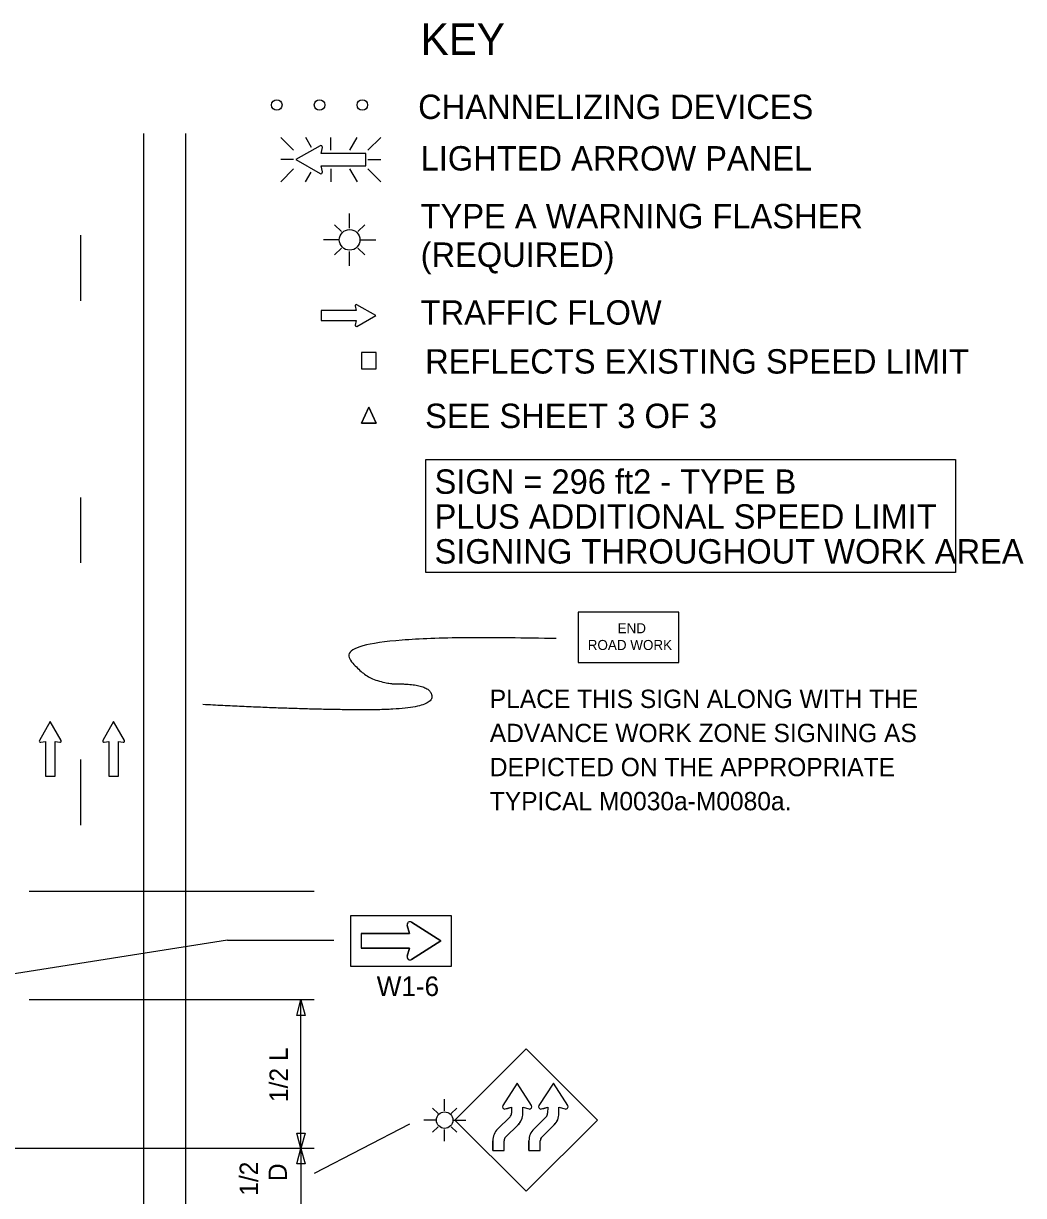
# Model space of a CAD drawing. Extents: x 16544 to 19504, y 5662 to 6922.
# Drawn here: x 17061.7 to 17442.9, y 6474.9 to 6922 of the extents above; entities that cross this region are included whole.
import ezdxf

# ---------------------------------------------------------------- set-up
doc = ezdxf.new("R2010")
doc.units = 0
for name, color, linetype in [('ALI_LEGAL_EX', 7, 'Continuous'), ('MT_SCRATCH_LEVEL_E', 7, 'Continuous'), ('PAVT_EDGE_EX', 7, 'Continuous'), ('TRAFFIC_SIGNS_PR', 7, 'Continuous'), ('TYPICAL_TEXT_DIMEN_EX', 7, 'Continuous'), ('TYPICAL_TEXT_DIMEN_PR', 7, 'Continuous')]:
    doc.layers.add(name, color=color, linetype=linetype)

msp = doc.modelspace()

# ---------------------------------------------------------------- linework, layer by layer
at = {"layer": 'ALI_LEGAL_EX'}
for points in [[(17083.46, 6841.23), (17083.46, 6816.23)], [(17083.46, 6741.23), (17083.46, 6716.23)], [(17083.46, 6641.23), (17083.46, 6616.23)]]:
    msp.add_lwpolyline(points, dxfattribs=at)
at = {"layer": 'MT_SCRATCH_LEVEL_E'}
for p, q in [((17188.13, 6814.25), (17188.44, 6812.47)), ((17188.13, 6814.25), (17188.44, 6812.47)), ((17196.05, 6810.62), (17188.81, 6814.73)), ((17196.05, 6810.62), (17188.81, 6814.73)), ((17188.44, 6812.47), (17175.19, 6812.47)), ((17175.19, 6812.47), (17175.19, 6808.73)), ((17188.44, 6812.47), (17175.19, 6812.47)), ((17175.19, 6812.47), (17175.19, 6808.73)), ((17188.81, 6806.47), (17196.05, 6810.62)), ((17188.81, 6806.47), (17196.05, 6810.62)), ((17175.19, 6808.73), (17188.44, 6808.73)), ((17175.19, 6808.73), (17188.44, 6808.73)), ((17188.44, 6808.73), (17188.13, 6806.95)), ((17188.44, 6808.73), (17188.13, 6806.95)), ((17071.87, 6655.73), (17067.76, 6648.49)), ((17071.87, 6655.73), (17067.76, 6648.49)), ((17076.02, 6648.49), (17071.87, 6655.73)), ((17076.02, 6648.49), (17071.87, 6655.73)), ((17096.04, 6655.73), (17091.93, 6648.49)), ((17096.04, 6655.73), (17091.93, 6648.49)), ((17100.19, 6648.49), (17096.04, 6655.73)), ((17100.19, 6648.49), (17096.04, 6655.73)), ((17068.24, 6647.81), (17070.02, 6648.12)), ((17068.24, 6647.81), (17070.02, 6648.12)), ((17070.02, 6648.12), (17070.02, 6634.86)), ((17070.02, 6648.12), (17070.02, 6634.86)), ((17073.76, 6634.86), (17073.76, 6648.12)), ((17073.76, 6648.12), (17075.54, 6647.81)), ((17073.76, 6634.86), (17073.76, 6648.12)), ((17073.76, 6648.12), (17075.54, 6647.81)), ((17092.41, 6647.81), (17094.19, 6648.12)), ((17092.41, 6647.81), (17094.19, 6648.12)), ((17094.19, 6648.12), (17094.19, 6634.86)), ((17094.19, 6648.12), (17094.19, 6634.86)), ((17097.93, 6634.86), (17097.93, 6648.12)), ((17097.93, 6648.12), (17099.71, 6647.81)), ((17097.93, 6634.86), (17097.93, 6648.12)), ((17097.93, 6648.12), (17099.71, 6647.81)), ((17070.02, 6634.86), (17073.76, 6634.86)), ((17070.02, 6634.86), (17073.76, 6634.86)), ((17094.19, 6634.86), (17097.93, 6634.86)), ((17094.19, 6634.86), (17097.93, 6634.86))]:
    msp.add_line(p, q, dxfattribs=at)
for centre, start, end in [((17188.59, 6814.32), 60.4248, 189.9638), ((17188.59, 6814.32), 60.4248, 189.9638), ((17188.59, 6806.88), 170.0362, 299.7731), ((17188.59, 6806.88), 170.0362, 299.7731), ((17075.61, 6648.27), 260.0362, 29.7731), ((17075.61, 6648.27), 260.0362, 29.7731), ((17099.78, 6648.27), 260.0362, 29.7731), ((17099.78, 6648.27), 260.0362, 29.7731), ((17068.17, 6648.26), 150.4248, 279.9638), ((17068.17, 6648.26), 150.4248, 279.9638), ((17092.34, 6648.26), 150.4248, 279.9638), ((17092.34, 6648.26), 150.4248, 279.9638)]:
    msp.add_arc(centre, 0.463, start, end, dxfattribs=at)
at = {"layer": 'PAVT_EDGE_EX'}
for p, q in [((17107.46, 6880.02), (17107.46, 6074.05)), ((17123.46, 6880.02), (17123.46, 6074.05))]:
    msp.add_line(p, q, dxfattribs=at)
at = {"layer": 'TRAFFIC_SIGNS_PR'}
for p, q in [((17159.73, 6878.55), (17164.67, 6873.62)), ((17171.5, 6874.73), (17169.29, 6878.56)), ((17178.82, 6873.62), (17178.82, 6878.56)), ((17186.05, 6873.62), (17188.9, 6878.56)), ((17192.97, 6873.62), (17197.9, 6878.56)), ((17164.67, 6870.07), (17159.73, 6870.07)), ((17192.97, 6870.07), (17197.9, 6870.07)), ((17159.73, 6861.58), (17164.67, 6866.51)), ((17169.25, 6861.57), (17171.36, 6865.24)), ((17178.82, 6866.51), (17178.82, 6861.57)), ((17188.95, 6861.57), (17186.1, 6866.51)), ((17192.97, 6866.51), (17197.9, 6861.57)), ((17182.88, 6842.6), (17180.25, 6845.23)), ((17182.88, 6842.6), (17180.25, 6845.23)), ((17186.02, 6843.9), (17186.02, 6849.52)), ((17186.02, 6843.9), (17186.02, 6849.52)), ((17189.16, 6842.6), (17191.79, 6845.23)), ((17189.16, 6842.6), (17191.79, 6845.23)), ((17182.08, 6839.46), (17176.04, 6839.46)), ((17182.08, 6839.46), (17176.04, 6839.46)), ((17182.88, 6836.33), (17180.25, 6833.7)), ((17182.88, 6836.33), (17180.25, 6833.7)), ((17189.16, 6836.33), (17191.79, 6833.7)), ((17189.16, 6836.33), (17191.79, 6833.7)), ((17189.96, 6839.46), (17196.05, 6839.46)), ((17189.96, 6839.46), (17196.05, 6839.46)), ((17186.02, 6829.52), (17186.02, 6835.03)), ((17186.02, 6829.52), (17186.02, 6835.03)), ((17208.8, 6574.87), (17207.96, 6577.93)), ((17209.64, 6579.18), (17220.8, 6572.07)), ((17190.4, 6574.87), (17208.8, 6574.87)), ((17190.4, 6574.87), (17190.4, 6569.27)), ((17208.8, 6569.27), (17190.4, 6569.27)), ((17207.96, 6566.21), (17208.8, 6569.27)), ((17220.8, 6572.07), (17209.64, 6564.97)), ((17253.3, 6530.86), (17226.15, 6503.71)), ((17280.45, 6503.71), (17253.3, 6530.86)), ((17222.23, 6507.23), (17222.23, 6511.73)), ((17219.72, 6506.19), (17217.61, 6508.29)), ((17224.74, 6506.19), (17226.85, 6508.29)), ((17219.07, 6503.67), (17214.24, 6503.67)), ((17219.71, 6501.16), (17217.61, 6499.05)), ((17224.74, 6501.16), (17226.85, 6499.05)), ((17225.38, 6503.67), (17230.26, 6503.67)), ((17226.15, 6503.71), (17253.3, 6476.56)), ((17242.43, 6500.24), (17247.15, 6504.96)), ((17247.15, 6504.96), (17242.43, 6500.24)), ((17245.48, 6497.19), (17250.2, 6501.91)), ((17245.49, 6497.19), (17250.2, 6501.91)), ((17253.3, 6476.56), (17280.45, 6503.71)), ((17256.23, 6500.24), (17260.94, 6504.96)), ((17260.94, 6504.96), (17256.23, 6500.24)), ((17259.28, 6497.19), (17264, 6501.91)), ((17259.28, 6497.19), (17264, 6501.91)), ((17222.23, 6495.71), (17222.23, 6500.12)), ((17240.57, 6492.12), (17240.57, 6495.82)), ((17240.57, 6492.12), (17244.88, 6492.12)), ((17244.88, 6492.12), (17244.88, 6495.82)), ((17254.36, 6492.12), (17254.36, 6495.82)), ((17254.36, 6492.12), (17258.68, 6492.12)), ((17258.68, 6492.12), (17258.68, 6495.82))]:
    msp.add_line(p, q, dxfattribs=at)
for points in [[(17174.74, 6875.34), (17165.45, 6870.07), (17174.75, 6864.74)], [(17175.62, 6865.37), (17175.22, 6867.64), (17192.23, 6867.64), (17192.23, 6872.44), (17175.22, 6872.44), (17175.62, 6874.72)], [(17193.31, 6775.69), (17190.51, 6769.52)], [(17190.51, 6769.52), (17193.31, 6775.69)], [(17196.11, 6769.52), (17193.31, 6775.69)], [(17193.31, 6775.69), (17196.11, 6769.52)], [(17190.51, 6769.52), (17196.11, 6769.52)], [(17196.11, 6769.52), (17190.51, 6769.52)], [(17207.96, 6577.93), (17208.8, 6574.87), (17190.4, 6574.87), (17190.4, 6569.27), (17208.8, 6569.27), (17207.96, 6566.21)], [(17209.64, 6564.97), (17220.8, 6572.07), (17209.64, 6579.18)], [(17255.35, 6509.23), (17249.87, 6517.84), (17244.39, 6509.23)], [(17255.35, 6509.23), (17249.87, 6517.84), (17244.39, 6509.23)], [(17269.15, 6509.23), (17263.67, 6517.84), (17258.19, 6509.23)], [(17269.15, 6509.23), (17263.67, 6517.84), (17258.19, 6509.23)], [(17245.35, 6507.93), (17247.71, 6508.58), (17247.71, 6506.29)], [(17245.35, 6507.93), (17246.18, 6508.16), (17247.71, 6508.58), (17247.71, 6506.29)], [(17252.02, 6506.22), (17252.03, 6508.58), (17254.39, 6507.93)], [(17252.02, 6506.22), (17252.03, 6508.58), (17254.39, 6507.93)], [(17259.15, 6507.93), (17261.51, 6508.58), (17261.5, 6506.29)], [(17259.15, 6507.93), (17259.98, 6508.16), (17261.51, 6508.58), (17261.5, 6506.29)], [(17265.82, 6506.22), (17265.82, 6508.58), (17268.19, 6507.93)], [(17265.82, 6506.22), (17265.82, 6508.58), (17268.19, 6507.93)], [(17240.57, 6495.82), (17240.57, 6492.12), (17244.88, 6492.12), (17244.88, 6495.82)], [(17254.36, 6495.82), (17254.36, 6492.12), (17258.68, 6492.12), (17258.68, 6495.82)]]:
    msp.add_lwpolyline(points, dxfattribs=at)
for points in [[(17190.51, 6790.3), (17196.11, 6790.3), (17196.11, 6796.47), (17190.51, 6796.47)], [(17273.17, 6678.27), (17311.57, 6678.27), (17311.57, 6697.47), (17273.17, 6697.47)], [(17186.4, 6562.47), (17224.8, 6562.47), (17224.8, 6581.67), (17186.4, 6581.67)]]:
    msp.add_lwpolyline(points, close=True, dxfattribs=at)
for centre, radius in [((17158.24, 6890.91), 2), ((17174.54, 6890.91), 2), ((17190.84, 6890.91), 2), ((17186.02, 6839.46), 3.94), ((17186.02, 6839.46), 3.94), ((17222.23, 6503.67), 3.15)]:
    msp.add_circle(centre, radius, dxfattribs=at)
for centre, radius, start, end in [((17175.03, 6874.82), 0.598, 350.7308, 118.8916), ((17175.03, 6865.27), 0.597, 241.4833, 9.9593), ((17209.04, 6578.23), 1.12, 57.5304, 195.3269), ((17209.04, 6578.23), 1.12, 57.5304, 195.3269), ((17209.04, 6565.92), 1.12, 164.6731, 302.4696), ((17209.04, 6565.92), 1.12, 164.6731, 302.4696), ((17245.12, 6508.77), 0.866, 147.5288, 285.3852), ((17245.12, 6508.77), 0.864, 147.5204, 285.3986), ((17245.86, 6506.28), 1.85, 314.2123, 0.1238), ((17245.86, 6506.28), 1.85, 314.2125, 0), ((17245.86, 6506.28), 6.17, 314.2125, 359.3819), ((17245.86, 6506.28), 6.17, 314.7687, 359.3755), ((17254.62, 6508.77), 0.866, 254.6828, 32.2708), ((17254.62, 6508.77), 0.866, 254.6799, 32.2804), ((17251.54, 6497.52), 10.8, 74.68, 74.6808), ((17264.46, 6515.03), 10.8, 212.4569, 212.4665), ((17258.92, 6508.77), 0.864, 147.5204, 285.3986), ((17258.92, 6508.77), 0.866, 147.5288, 285.3852), ((17259.65, 6506.28), 1.85, 314.2123, 0.1238), ((17259.65, 6506.28), 1.85, 314.2125, 0), ((17259.65, 6506.28), 6.17, 314.2125, 359.3819), ((17259.65, 6506.28), 6.17, 314.7687, 359.3755), ((17268.42, 6508.77), 0.866, 254.6828, 32.2708), ((17268.42, 6508.77), 0.866, 254.6799, 32.2804), ((17265.33, 6497.52), 10.8, 74.68, 74.6808), ((17278.26, 6515.03), 10.8, 212.4569, 212.4665), ((17246.73, 6495.82), 6.17, 134.2125, 180), ((17246.73, 6495.82), 6.17, 134.2125, 180), ((17246.73, 6495.82), 6.17, 134.2117, 180), ((17246.73, 6495.82), 1.85, 132.372, 180), ((17246.73, 6495.82), 1.85, 134.2125, 180), ((17260.53, 6495.82), 6.17, 134.2125, 180), ((17260.53, 6495.82), 6.17, 134.2125, 180), ((17260.53, 6495.82), 6.17, 134.2117, 180), ((17260.53, 6495.82), 1.85, 132.372, 180), ((17260.53, 6495.82), 1.85, 134.2125, 180)]:
    msp.add_arc(centre, radius, start, end, dxfattribs=at)
at = {"layer": 'TYPICAL_TEXT_DIMEN_EX'}
msp.add_lwpolyline([(17215.05, 6755.7), (17416.96, 6755.7), (17416.96, 6712.54), (17215.05, 6712.54)], close=True, dxfattribs=at)
at = {"layer": 'TYPICAL_TEXT_DIMEN_PR'}
for p, q in [((17172.46, 6590.85), (17063.88, 6590.85)), ((17139.51, 6572.32), (16997.97, 6549.9)), ((17139.51, 6572.32), (17179.97, 6572.32)), ((17172.46, 6549.51), (17063.88, 6549.51)), ((17165.89, 6543.65), (17167.46, 6549.51)), ((17167.46, 6492.87), (17167.46, 6549.51)), ((17167.46, 6549.51), (17169.03, 6543.65)), ((17167.46, 6543.65), (17165.89, 6543.65)), ((17169.03, 6543.65), (17167.46, 6543.65)), ((17172.67, 6483.49), (17209.02, 6502.22)), ((17167.46, 6492.87), (17165.89, 6498.73)), ((17165.89, 6498.73), (17167.46, 6498.73)), ((17167.46, 6498.73), (17169.03, 6498.73)), ((17169.03, 6498.73), (17167.46, 6492.87)), ((17172.46, 6492.87), (16994.34, 6492.87)), ((17165.89, 6487.01), (17167.46, 6492.87)), ((17167.46, 6492.87), (17169.03, 6487.01)), ((17167.46, 6492.87), (17167.46, 6468.41)), ((17167.46, 6487.01), (17165.89, 6487.01)), ((17169.03, 6487.01), (17167.46, 6487.01))]:
    msp.add_line(p, q, dxfattribs=at)
msp.add_open_spline([(17264.78, 6687.38), (17180.07, 6689.39), (17192.19, 6670.08), (17217.36, 6670.08), (17217.36, 6660.18), (17167.72, 6660.18), (17130.08, 6662.2)], degree=2, dxfattribs=at)

# ---------------------------------------------------------------- texts
at = {"layer": 'TRAFFIC_SIGNS_PR'}
for s, height, p in [('END', 3.831, (17288.17, 6689.4)), ('ROAD WORK', 3.831, (17276.78, 6683.01)), ('PLACE THIS SIGN ALONG WITH THE', 7, (17239.44, 6660.87)), ('ADVANCE WORK ZONE SIGNING AS', 7, (17239.44, 6647.87)), ('DEPICTED ON THE APPROPRIATE', 7, (17239.44, 6634.87)), ('TYPICAL M0030a-M0080a.', 7, (17239.44, 6621.87)), ('W1-6', 7.44, (17196.34, 6551.03))]:
    msp.add_text(s, height=height, dxfattribs=at).set_placement(p)
at = {"layer": 'TYPICAL_TEXT_DIMEN_EX'}
for s, height, p in [('KEY', 12, (17213.08, 6910.01)), ('CHANNELIZING DEVICES', 9.3, (17212.13, 6885.57)), ('LIGHTED ARROW PANEL', 9.3, (17213.08, 6865.91)), ('TYPE A WARNING FLASHER', 9.3, (17213.08, 6843.86)), ('(REQUIRED)', 9.3, (17213.08, 6829.16)), ('TRAFFIC FLOW', 9.3, (17213.08, 6807.11)), ('REFLECTS EXISTING SPEED LIMIT', 9.3, (17214.79, 6788.46)), ('SEE SHEET 3 OF 3', 9.3, (17214.79, 6767.68)), ('SIGN = 296 ft2 - TYPE B', 9.3, (17218.39, 6742.59)), ('PLUS ADDITIONAL SPEED LIMIT', 9.3, (17218.39, 6729.29)), ('SIGNING THROUGHOUT WORK AREA', 9.3, (17218.39, 6715.99))]:
    msp.add_text(s, height=height, dxfattribs=at).set_placement(p)
at = {"layer": 'TYPICAL_TEXT_DIMEN_PR'}
for s, p in [('1/2 L', (17162.46, 6510.57)), ('1/2', (17151.09, 6474.83)), ('D', (17162.09, 6480.4))]:
    msp.add_text(s, height=7, rotation=90, dxfattribs=at).set_placement(p)

doc.saveas('drawing.dxf')
